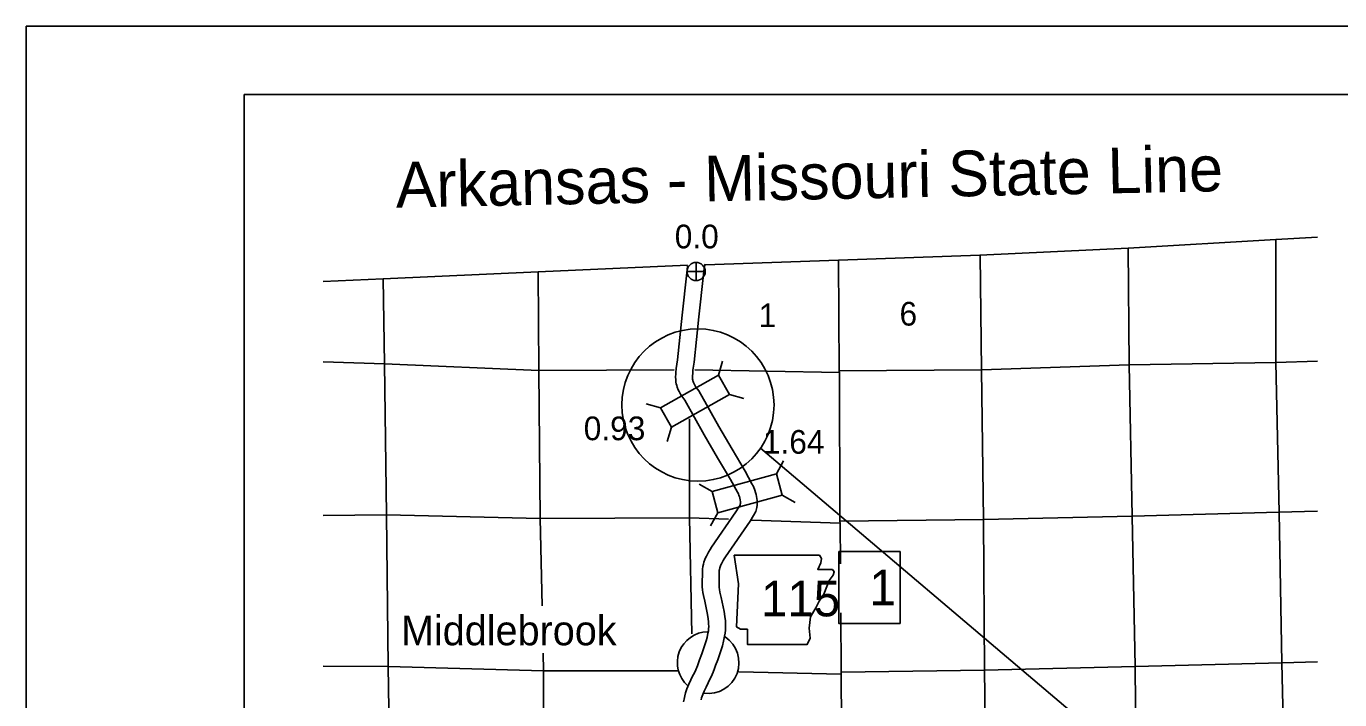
# Model space of a CAD drawing. Extents: x 1369885 to 1370219, y 379980 to 380218.
# Drawn here: x 1369885.4 to 1369960.2, y 380179.6 to 380217.9 of the extents above; entities that cross this region are included whole.
import ezdxf

# ---------------------------------------------------------------- set-up
doc = ezdxf.new("R2010")
doc.units = 0
for name, color, linetype in [('Default', 7, 'Continuous'), ('Level 1', 7, 'Continuous'), ('Level 10', 7, 'Continuous'), ('Level 20', 7, 'Continuous'), ('Level 21', 7, 'Continuous'), ('Level 24', 7, 'Continuous'), ('Level 25', 7, 'Continuous'), ('Level 26', 7, 'Continuous'), ('Level 27', 7, 'Continuous'), ('Level 4', 7, 'Continuous'), ('Level 5', 7, 'Continuous'), ('Level 58', 7, 'Continuous'), ('R_No Plot', 7, 'Continuous'), ('STAMP_PE_FOSTER-SIGNATURE', 7, 'Continuous')]:
    doc.layers.add(name, color=color, linetype=linetype)

msp = doc.modelspace()

# ---------------------------------------------------------------- linework, layer by layer
at = {"layer": 'Default'}
msp.add_line((1369969.714, 380157.907), (1369927.244, 380193.89), dxfattribs=at)
msp.add_circle((1369923.675, 380196.352), 4.335, dxfattribs=at)
at = {"layer": 'Level 1'}
for points in [[(1369948.189, 380205.291), (1369939.742, 380204.883), (1369931.689, 380204.61), (1369924.084, 380204.343)], [(1369958.986, 380205.905), (1369956.602, 380205.77), (1369948.189, 380205.291)], [(1369923.085, 380204.308), (1369914.563, 380203.931), (1369905.738, 380203.537), (1369902.311, 380203.384)]]:
    msp.add_lwpolyline(points, dxfattribs=at)
at = {"layer": 'Level 10'}
for points in [[(1369923.086, 380204.292), (1369923.08, 380204.252), (1369923.041, 380203.884), (1369922.783, 380201.471), (1369922.505, 380198.916), (1369922.439, 380198.433), (1369922.42, 380198.203), (1369922.414, 380198.089), (1369922.403, 380197.969), (1369922.415, 380197.757), (1369922.423, 380197.656), (1369922.438, 380197.564), (1369922.463, 380197.466), (1369922.492, 380197.359), (1369922.556, 380197.218), (1369922.606, 380197.114), (1369922.683, 380196.976), (1369922.752, 380196.85), (1369922.925, 380196.627), (1369924.032, 380194.649), (1369924.795, 380193.345), (1369925.525, 380192.103), (1369925.922, 380191.393), (1369925.977, 380191.298), (1369926.014, 380191.205), (1369926.034, 380191.132), (1369926.055, 380191.041), (1369926.078, 380190.947), (1369926.094, 380190.839), (1369926.095, 380190.786), (1369926.095, 380190.737), (1369926.088, 380190.703), (1369926.082, 380190.673), (1369926.075, 380190.647), (1369926.014, 380190.54), (1369925.842, 380190.266), (1369924.453, 380188.251), (1369924.365, 380188.121), (1369924.27, 380187.976), (1369924.197, 380187.825), (1369924.157, 380187.737), (1369924.114, 380187.654), (1369924.07, 380187.554), (1369924.013, 380187.407), (1369923.985, 380187.281), (1369923.957, 380187.148), (1369923.935, 380187), (1369923.919, 380185.99), (1369923.93, 380185.831), (1369923.961, 380185.669), (1369923.988, 380185.501), (1369924.066, 380185.186), (1369924.222, 380184.418), (1369924.263, 380184.175), (1369924.281, 380183.998), (1369924.285, 380183.886), (1369924.288, 380183.741), (1369924.282, 380183.603), (1369924.269, 380183.491), (1369924.245, 380183.356), (1369924.201, 380183.106), (1369924.151, 380182.911), (1369923.903, 380182.175), (1369923.771, 380181.845), (1369923.71, 380181.661), (1369923.646, 380181.497), (1369923.554, 380181.273), (1369923.452, 380181.068), (1369923.392, 380180.937), (1369923.278, 380180.701), (1369923.153, 380180.446), (1369923.051, 380180.193), (1369922.97, 380179.954), (1369922.924, 380179.785), (1369922.883, 380179.605), (1369922.856, 380179.438)], [(1369924.084, 380204.364), (1369924.071, 380204.31), (1369924.042, 380204.206), (1369924.03, 380204.128), (1369923.994, 380203.782), (1369923.735, 380201.368), (1369923.456, 380198.799), (1369923.392, 380198.328), (1369923.376, 380198.14), (1369923.371, 380198.022), (1369923.364, 380197.95), (1369923.371, 380197.822), (1369923.375, 380197.77), (1369923.377, 380197.76), (1369923.389, 380197.712), (1369923.396, 380197.685), (1369923.424, 380197.624), (1369923.456, 380197.558), (1369923.523, 380197.439), (1369923.557, 380197.376), (1369923.726, 380197.157), (1369924.863, 380195.125), (1369925.621, 380193.83), (1369926.357, 380192.58), (1369926.754, 380191.869), (1369926.842, 380191.719), (1369926.925, 380191.509), (1369926.964, 380191.366), (1369926.988, 380191.26), (1369927.019, 380191.132), (1369927.053, 380190.914), (1369927.053, 380190.788), (1369927.053, 380190.651), (1369927.028, 380190.511), (1369927.012, 380190.443), (1369926.969, 380190.282), (1369926.838, 380190.049), (1369926.642, 380189.739), (1369925.244, 380187.71), (1369925.162, 380187.589), (1369925.106, 380187.504), (1369925.066, 380187.42), (1369925.018, 380187.313), (1369924.978, 380187.239), (1369924.957, 380187.189), (1369924.933, 380187.128), (1369924.922, 380187.08), (1369924.901, 380186.98), (1369924.892, 380186.922), (1369924.878, 380186.014), (1369924.882, 380185.955), (1369924.905, 380185.837), (1369924.928, 380185.692), (1369925.001, 380185.397), (1369925.165, 380184.593), (1369925.214, 380184.301), (1369925.238, 380184.063), (1369925.243, 380183.912), (1369925.246, 380183.731), (1369925.239, 380183.529), (1369925.218, 380183.351), (1369925.189, 380183.188), (1369925.138, 380182.903), (1369925.071, 380182.639), (1369924.802, 380181.843), (1369924.671, 380181.516), (1369924.611, 380181.336), (1369924.536, 380181.142), (1369924.428, 380180.878), (1369924.316, 380180.652), (1369924.258, 380180.528), (1369924.141, 380180.282), (1369924.029, 380180.054), (1369923.949, 380179.858), (1369923.887, 380179.675), (1369923.854, 380179.553)]]:
    msp.add_lwpolyline(points, dxfattribs=at)
at = {"layer": 'Level 20'}
for p, q in [((1369924.854, 380198.045), (1369925.083, 380198.857)), ((1369921.543, 380196.192), (1369920.731, 380196.421)), ((1369925.472, 380196.942), (1369926.284, 380196.713)), ((1369922.161, 380195.088), (1369921.931, 380194.276)), ((1369928.143, 380192.431), (1369928.56, 380193.164)), ((1369924.482, 380191.428), (1369923.75, 380191.846)), ((1369928.477, 380191.211), (1369929.21, 380190.793)), ((1369924.817, 380190.208), (1369924.399, 380189.476))]:
    msp.add_line(p, q, dxfattribs=at)
for points in [[(1369922.161, 380195.088), (1369925.472, 380196.942), (1369924.854, 380198.045), (1369921.543, 380196.192)], [(1369924.817, 380190.208), (1369928.477, 380191.211), (1369928.143, 380192.431), (1369924.482, 380191.428)]]:
    msp.add_lwpolyline(points, close=True, dxfattribs=at)
at = {"layer": 'Level 21'}
msp.add_lwpolyline([(1369925.742, 380187.794), (1369925.985, 380186.173), (1369925.877, 380183.714), (1369926.093, 380183.579), (1369926.498, 380183.579), (1369926.498, 380182.714), (1369929.903, 380182.714), (1369930.065, 380183.065), (1369930.011, 380183.633), (1369930.092, 380184.281), (1369930.39, 380184.795), (1369930.579, 380185.173), (1369930.849, 380185.578), (1369931.011, 380186.011), (1369931.146, 380186.362), (1369931.389, 380186.659), (1369931.443, 380186.848), (1369931.335, 380186.983), (1369930.498, 380186.983), (1369930.687, 380187.362), (1369930.714, 380187.605), (1369930.602, 380187.792)], close=True, dxfattribs=at)
at = {"layer": 'Level 24'}
for start, end in [(90.87244, 228.67826), (262.19591, 56.55101)]:
    msp.add_arc((1369924.258, 380181.68), 1.757, start, end, dxfattribs=at)
at = {"layer": 'Level 26'}
for p, q in [((1369923.052, 380203.953), (1369924.09, 380203.953)), ((1369923.571, 380203.434), (1369923.571, 380204.472))]:
    msp.add_line(p, q, dxfattribs=at)
msp.add_circle((1369923.571, 380203.953), 0.519, dxfattribs=at)
at = {"layer": 'Level 27'}
msp.add_lwpolyline([(1369931.701, 380188.002), (1369935.19, 380188.002), (1369935.19, 380183.914), (1369931.701, 380183.914)], close=True, dxfattribs=at)
at = {"layer": 'Level 4'}
for points in [[(1369931.689, 380204.61), (1369931.727, 380198.293), (1369931.735, 380198.207), (1369931.766, 380189.733), (1369931.779, 380189.621), (1369931.795, 380187.313)], [(1369931.814, 380184.515), (1369931.837, 380181.126), (1369931.833, 380181.027), (1369931.902, 380172.561), (1369931.901, 380172.481), (1369931.907, 380170.949)]]:
    msp.add_lwpolyline(points, dxfattribs=at)
at = {"layer": 'Level 5'}
for points in [[(1369948.189, 380205.291), (1369948.248, 380198.638), (1369948.425, 380190.028), (1369948.583, 380181.454), (1369948.675, 380172.819), (1369948.725, 380167.527)], [(1369957.093, 380175.151), (1369956.953, 380181.666), (1369956.793, 380190.233), (1369956.598, 380198.769), (1369956.602, 380205.77)], [(1369940.235, 380161.925), (1369940.222, 380164.017), (1369940.127, 380172.612), (1369940.009, 380181.258), (1369939.946, 380189.836), (1369939.826, 380198.359), (1369939.763, 380204.868)], [(1369914.798, 380184.918), (1369914.694, 380189.878), (1369914.613, 380198.311), (1369914.563, 380203.931)], [(1369905.738, 380203.537), (1369905.818, 380198.693), (1369905.933, 380190.092), (1369906.032, 380181.452), (1369906.147, 380173.018), (1369906.209, 380164.33), (1369906.42, 380155.85)], [(1369902.311, 380198.803), (1369905.818, 380198.693), (1369914.613, 380198.311), (1369922.319, 380198.36)], [(1369931.727, 380198.293), (1369939.826, 380198.359), (1369948.248, 380198.638)], [(1369948.248, 380198.638), (1369956.598, 380198.769), (1369958.986, 380198.85)], [(1369923.492, 380198.359), (1369931.735, 380198.207)], [(1369923.187, 380195.573), (1369923.203, 380189.916), (1369923.329, 380183.318)], [(1369925.416, 380189.84), (1369923.203, 380189.916), (1369914.694, 380189.878), (1369905.933, 380190.092), (1369902.311, 380190.066)], [(1369931.779, 380189.621), (1369926.73, 380189.795)], [(1369948.425, 380190.028), (1369939.946, 380189.836), (1369931.766, 380189.733)], [(1369958.986, 380190.308), (1369956.779, 380190.252), (1369948.425, 380190.028)], [(1369914.997, 380155.591), (1369914.944, 380164.166), (1369914.846, 380172.646), (1369914.877, 380181.207), (1369914.855, 380182.213)], [(1369902.311, 380181.47), (1369906.032, 380181.452), (1369914.877, 380181.207), (1369922.514, 380181.212)], [(1369931.837, 380181.126), (1369940.009, 380181.258), (1369948.583, 380181.454)], [(1369948.583, 380181.454), (1369956.953, 380181.666), (1369958.986, 380181.722)], [(1369926, 380181.155), (1369931.833, 380181.027)]]:
    msp.add_lwpolyline(points, dxfattribs=at)
at = {"layer": 'R_No Plot'}
msp.add_line((1369885.407, 380217.922), (1370218.741, 380217.922), dxfattribs=at)
msp.add_lwpolyline([(1369885.401, 380217.922), (1370218.741, 380217.922), (1370218.741, 380004.585), (1369885.401, 380004.585)], close=True, dxfattribs=at)
at = {"layer": 'STAMP_PE_FOSTER-SIGNATURE'}
for p, q in [((1369897.808, 380214.028), (1370213.988, 380214.028)), ((1369897.808, 380008.568), (1369897.808, 380214.028))]:
    msp.add_line(p, q, dxfattribs=at)

# ---------------------------------------------------------------- texts
at = {"layer": 'Default'}
msp.add_text('Arkansas - Missouri State Line', height=2.6, rotation=1.14962, dxfattribs=at).set_placement((1369906.475, 380207.587))
at = {"layer": 'Level 21'}
msp.add_text('115', height=2.024, dxfattribs=at).set_placement((1369927.266, 380184.314))
at = {"layer": 'Level 24'}
msp.add_text('Middlebrook', height=1.68668, dxfattribs=at).set_placement((1369906.754, 380182.666))
at = {"layer": 'Level 25'}
msp.add_text('0.0', height=1.3493, dxfattribs=at).set_placement((1369922.354, 380205.274))
at = {"layer": 'Level 27'}
msp.add_text('1', height=2.024, dxfattribs=at).set_placement((1369933.446, 380184.946))
at = {"layer": 'Level 5'}
for s, p in [('1', (1369927.139, 380200.786)), ('6', (1369935.161, 380200.875))]:
    msp.add_text(s, height=1.349, dxfattribs=at).set_placement(p)
at = {"layer": 'Level 58'}
for s, p in [('0.93', (1369917.167, 380194.346)), ('1.64', (1369927.374, 380193.577))]:
    msp.add_text(s, height=1.3493, dxfattribs=at).set_placement(p)

doc.saveas('drawing.dxf')
